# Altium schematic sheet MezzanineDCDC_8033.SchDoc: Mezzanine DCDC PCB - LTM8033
size B; Date: 9/7/2021; Engineer: J. Juneau; DocumentNumber: 1006; Revision: 1.2; SheetNumber: 3; SheetTotal: 4
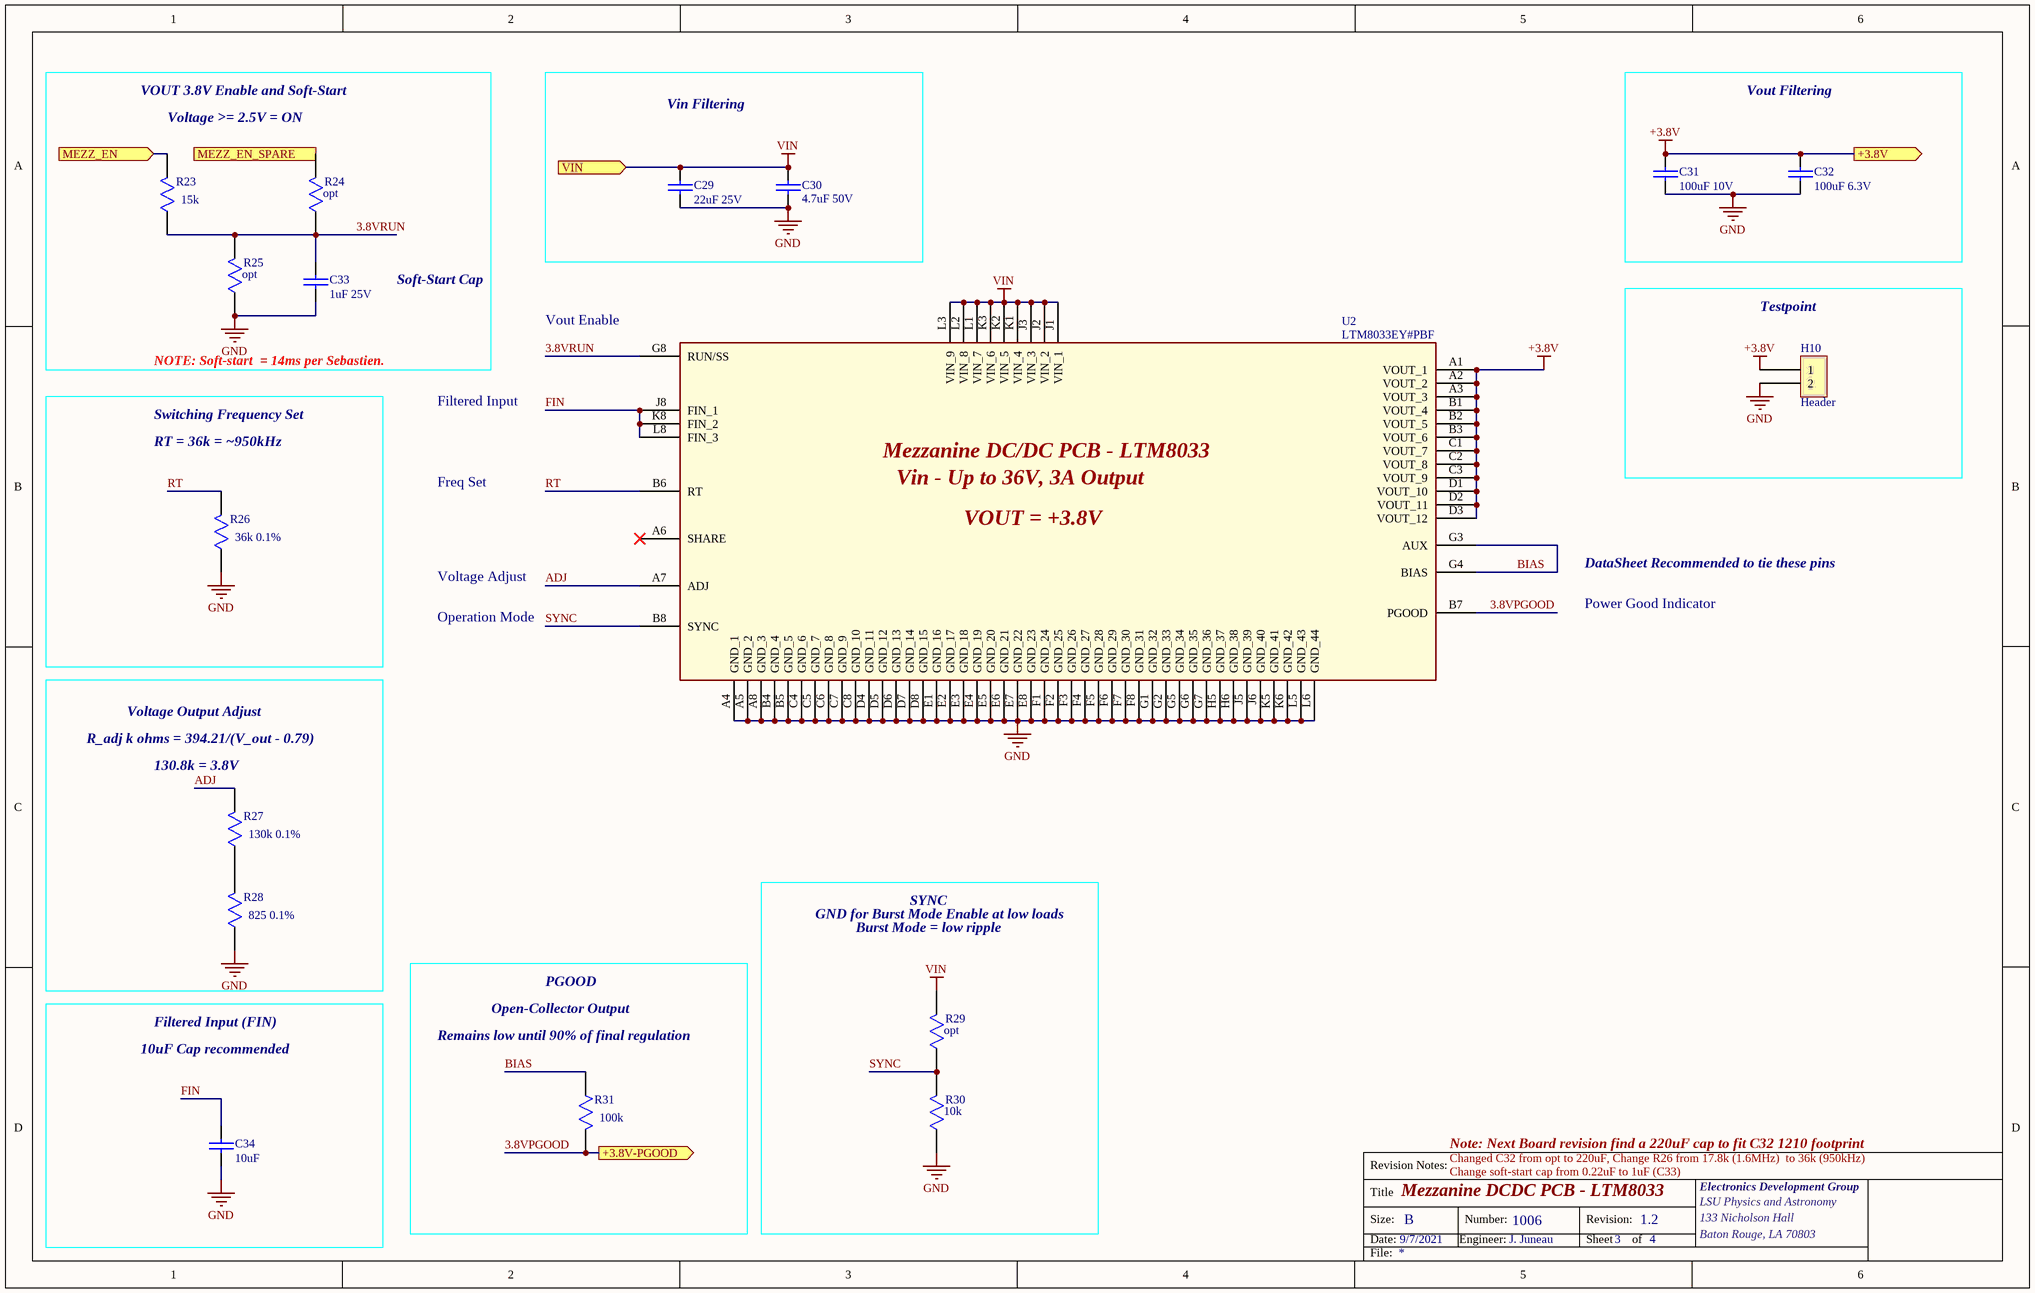
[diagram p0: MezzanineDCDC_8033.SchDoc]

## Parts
C29  value 22uF 25V  [CAP 1210 Murata]  (hidden comment: GRM32ER61E226KE15L)
C30  value 4.7uF 50V  [CAP 1206 TDK]  (hidden comment: UMK316BJ475KL-T)
C31  value 100uF 10V  [CAP 1210 Murata]  (hidden comment: LMK325BJ107MM-T)
C32  value 100uF 6.3V  [CAP 1210 Murata]  (hidden comment: GRM31CR60J227ME11L)
C33  value 1uF 25V  [Cap 0603 TDK]  (hidden comment: 06033C105KAT4A)
C34  value 10uF  [CAP 1210 Murata]  (hidden comment: GRM32ER71H106KA12L)
H10  Header  [Header 2Pin]
R23  value 15k  [Resistor ERJ2G/CRCW 0402]  (hidden comment: ERJ-U02F1502X)
R24  opt  [Resistor ERJ2G/CRCW 0402]
R25  opt  [Resistor ERJ2G/CRCW 0402]
R26  value 36k 0.1%  [Resistor 0603 - ERJ]  (hidden comment: ERA-3APB363V)
R27  value 130k 0.1%  [Resistor 0603 - ERJ]  (hidden comment: ERA-3AEB134V)
R28  value 825 0.1%  [Resistor 0603 - ERJ]  (hidden comment: ERA-3AEB8250V)
R29  opt  [Resistor ERJ2G/CRCW 0402]
R30  value 10k  [Resistor ERJ2G/CRCW 0402]  (hidden comment: ERJ-2GEJ103X)
R31  value 100k  [Resistor ERJ2G/CRCW 0402]  (hidden comment: ERJ-2RKF1003X)
U2  LTM8033EY#PBF  [LTM8033 BGA]

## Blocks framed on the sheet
Vin Filtering: C29 C30
Vout Filtering: C31 C32
Testpoint: H10

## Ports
+3.8V (out), +3.8V-PGOOD (out), MEZZ_EN (in), MEZZ_EN_SPARE (in), VIN (in)

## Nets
+3.8V: C31.1 C32.1 H10.1 U2.A1(VOUT_1) U2.A2(VOUT_2) U2.A3(VOUT_3) U2.B1(VOUT_4) U2.B2(VOUT_5) U2.B3(VOUT_6) U2.C1(VOUT_7) U2.C2(VOUT_8) U2.C3(VOUT_9) U2.D1(VOUT_10) U2.D2(VOUT_11) U2.D3(VOUT_12) ; port +3.8V
GND: C29.2 C30.2 C31.2 C32.2 C33.2 C34.2 H10.2 R25.1 R26.1 R28.1 R30.1 U2.A4(GND_1) U2.A5(GND_2) U2.A8(GND_3) U2.B4(GND_4) U2.B5(GND_5) U2.C4(GND_6) U2.C5(GND_7) U2.C6(GND_8) U2.C7(GND_9) U2.C8(GND_10) U2.D4(GND_11) U2.D5(GND_12) U2.D6(GND_13) U2.D7(GND_14) U2.D8(GND_15) U2.E1(GND_16) U2.E2(GND_17) U2.E3(GND_18) U2.E4(GND_19) U2.E5(GND_20) U2.E6(GND_21) U2.E7(GND_22) U2.E8(GND_23) U2.F1(GND_24) U2.F2(GND_25) U2.F3(GND_26) U2.F4(GND_27) U2.F5(GND_28) U2.F6(GND_29) U2.F7(GND_30) U2.F8(GND_31) U2.G1(GND_32) U2.G2(GND_33) U2.G5(GND_34) U2.G6(GND_35) U2.G7(GND_36) U2.H5(GND_37) U2.H6(GND_38) U2.J5(GND_39) U2.J6(GND_40) U2.K5(GND_41) U2.K6(GND_42) U2.L5(GND_43) U2.L6(GND_44)
VIN: C29.1 C30.1 R29.2 U2.J1(VIN_1) U2.J2(VIN_2) U2.J3(VIN_3) U2.K1(VIN_4) U2.K2(VIN_5) U2.K3(VIN_6) U2.L1(VIN_7) U2.L2(VIN_8) U2.L3(VIN_9) ; port VIN
3.8VPGOOD: R31.2 U2.B7(PGOOD) ; port +3.8V-PGOOD
3.8VRUN: C33.1 R23.1 R24.1 R25.2 U2.G8(RUN/SS)
ADJ: R27.2 U2.A7(ADJ)
BIAS: R31.1 U2.G3(AUX) U2.G4(BIAS)
FIN: C34.1 U2.J8(FIN_1) U2.K8(FIN_2) U2.L8(FIN_3)
MEZZ_EN: R23.2 ; port MEZZ_EN
MEZZ_EN_SPARE: R24.2 ; port MEZZ_EN_SPARE
RT: R26.2 U2.B6(RT)
SYNC: R29.1 R30.2 U2.B8(SYNC)
NetR27_1: R27.1 R28.2

Not connected (* = marked no-connect by the designer): U2 A6(SHARE)*

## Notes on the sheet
- VOUT 3.8V Enable and Soft-Start
- Voltage >= 2.5V = ON
- Soft-Start Cap
- NOTE: Soft-start  = 14ms per Sebastien.
- Vout Enable
- Switching Frequency Set
- Filtered Input
- RT = 36k = ~950kHz
- Freq Set
- (near U2) Mezzanine DC/DC PCB - LTM8033
- (near U2) Vin - Up to 36V, 3A Output
- (near U2) VOUT = +3.8V
- DataSheet Recommended to tie these pins
- Voltage Adjust
- Operation Mode
- Power Good Indicator
- R_adj k ohms = 394.21/(V_out - 0.79)
- Voltage Output Adjust
- (near R27) 130.8k = 3.8V
- SYNC
- GND for Burst Mode Enable at low loads
- Burst Mode = low ripple
- Filtered Input (FIN)
- (near R31) Remains low until 90% of final regulation
- Open-Collector Output
- PGOOD
- 10uF Cap recommended
- Changed C32 from opt to 220uF, Change R26 from 17.8k (1.6MHz)  to 36k (950kHz)
- Note: Next Board revision find a 220uF cap to fit C32 1210 footprint
- Change soft-start cap from 0.22uF to 1uF (C33)

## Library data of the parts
C29 = Capacitor 1210: 22µF ±10% 25V Ceramic Capacitor X5R 1210 (3225 Metric)
C30 = Capacitor 1206: 4.7µF ±10% 50V Ceramic Capacitor X5R 1206 (3216 Metric)
C31 = Capacitor 1210: CAP CER 100UF 10V X5R 1210
C32 = Capacitor 1210: 220 µF ±20% 6.3V Ceramic Capacitor X5R 1206 (3216 Metric)
C33 = Capacitor 0603 TDK: 1 µF ±10% 25V Ceramic Capacitor X7R 0603 (1608 Metric)
C34 = Capacitor 1210: CAP CER 10UF 50V X7R 1210
H10 = Header - 2Pin: Connector Header Through Hole 2 position 0.100" (2.54mm)
R23 = ERJ2G Resistor 0402: RES 15K OHM 1% 1/10W 0402 SMD
R24 R25 R29 = ERJ2G Resistor 0402: Resistor 0402
R26 = Resistor 0603: 36 kOhms ±0.1% 0.1W, 1/10W Chip Resistor 0603 (1608 Metric) Automotive AEC-Q200 Thin Film
R27 = Resistor 0603: RES SMD 130K OHM 0.1% 1/10W 0603
R28 = Resistor 0603: RES SMD 825 OHM 0.1% 1/10W 0603
R30 = ERJ2G Resistor 0402: RES SMD 10K OHM 5% 1/10W 0402
R31 = ERJ2G Resistor 0402: RES SMD 100K OHM 1% 1/10W 0402
U2 = LTM8033: Non-Isolated PoL Module DC DC Converter Output 0.8 ~ 24V - - 3A 3.6V - 36V Input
